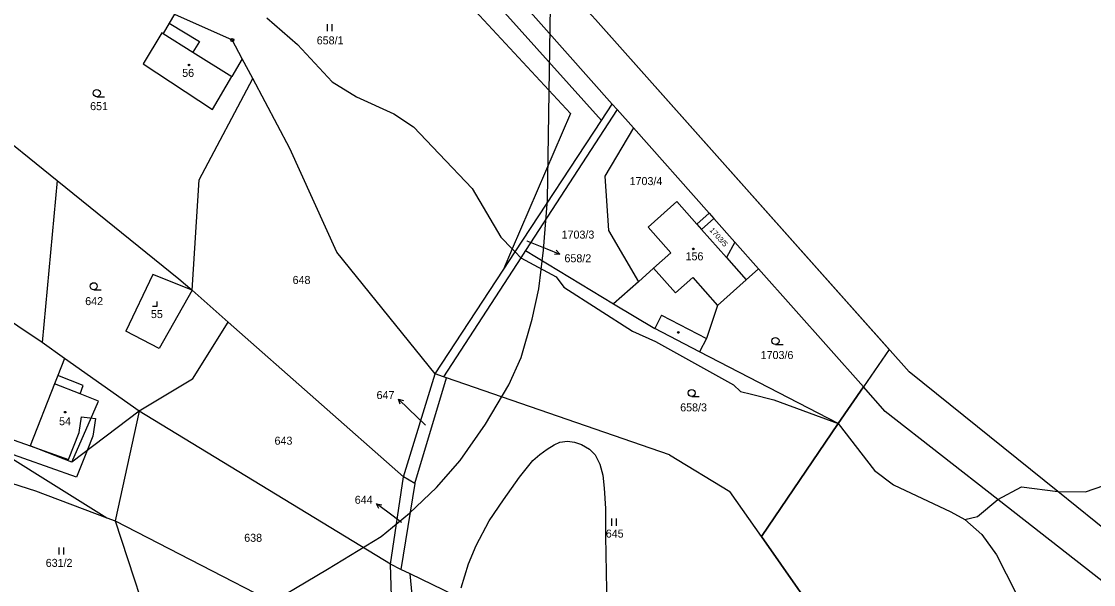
# Model space of a CAD drawing. Extents: x -546762 to -540209, y -1046851 to -1035694.
# Drawn here: x -544180.8 to -543953, y -1042709.8 to -1042590.2 of the extents above; entities that cross this region are included whole.
import ezdxf

# ---------------------------------------------------------------- set-up
doc = ezdxf.new("R2010")
doc.units = 0
for name, color, linetype in [('Vrstva 1', 7, 'Continuous'), ('Vrstva 16', 7, 'Continuous'), ('Vrstva 18', 7, 'Continuous'), ('Vrstva 19', 7, 'Continuous'), ('Vrstva 24', 7, 'Continuous'), ('Vrstva 25', 7, 'Continuous'), ('Vrstva 3', 7, 'Continuous'), ('Vrstva 30', 7, 'Continuous'), ('Vrstva 37', 7, 'Continuous'), ('Vrstva 4', 7, 'Continuous'), ('Vrstva 52', 7, 'Continuous')]:
    doc.layers.add(name, color=color, linetype=linetype)

msp = doc.modelspace()

# ---------------------------------------------------------------- linework, layer by layer
at = {"layer": 'Vrstva 1'}
for points in [[(-544055.22, -1042607.7), (-544128.99, -1042524.65)], [(-544133.73, -1042526.32), (-544057.53, -1042611.21)], [(-544064.09, -1042609.7), (-544135.03, -1042533.32)], [(-544148.22, -1042588.65), (-544149.36, -1042590.55)], [(-544148.22, -1042588.65), (-544135.96, -1042594.1)], [(-544149.36, -1042590.55), (-544150.68, -1042592.73)], [(-543992.15, -1042664.59), (-544058.8, -1042589.78)], [(-544150.93, -1042592.57), (-544154.93, -1042599.2)], [(-544150.68, -1042592.73), (-544150.93, -1042592.57)], [(-544133.85, -1042598.08), (-544135.96, -1042594.1)], [(-544133.85, -1042598.08), (-544136.06, -1042601.86)], [(-544131.62, -1042602.28), (-544133.85, -1042598.08)], [(-544154.93, -1042599.2), (-544140.19, -1042608.89)], [(-544142.98, -1042623.77), (-544131.62, -1042602.28)], [(-544140.19, -1042608.89), (-544136.06, -1042601.86)], [(-544123.71, -1042617.13), (-544131.62, -1042602.28)], [(-544054.18, -1042608.88), (-544073.66, -1042638.83)], [(-544057.53, -1042611.21), (-544055.22, -1042607.7)], [(-544054.18, -1042608.88), (-544055.22, -1042607.7)], [(-544050.73, -1042612.77), (-544054.18, -1042608.88)], [(-544188.45, -1042611.64), (-544173.21, -1042623.91)], [(-544064.09, -1042609.7), (-544076.47, -1042638.47)], [(-544075.86, -1042639.09), (-544057.53, -1042611.21)], [(-544050.73, -1042612.77), (-544056.83, -1042622.99)], [(-544034.62, -1042630.89), (-544050.73, -1042612.77)], [(-544113.77, -1042639.15), (-544123.71, -1042617.13)], [(-544056.83, -1042622.99), (-544055.99, -1042634.56)], [(-544173.21, -1042623.91), (-544176.39, -1042658.34)], [(-544173.21, -1042623.91), (-544147.29, -1042644.79)], [(-544144.5, -1042647.26), (-544142.98, -1042623.77)], [(-544041.49, -1042628.43), (-544047.62, -1042633.88)], [(-544041.49, -1042628.43), (-544037.23, -1042633.22)], [(-544037.23, -1042633.22), (-544034.62, -1042630.89)], [(-544033.62, -1042632.01), (-544036.24, -1042634.34)], [(-544034.62, -1042630.89), (-544033.62, -1042632.01)], [(-544033.62, -1042632.01), (-544029.17, -1042637.02)], [(-544055.99, -1042634.56), (-544049.65, -1042645.44)], [(-544042.77, -1042639.33), (-544047.62, -1042633.88)], [(-544036.24, -1042634.34), (-544030.92, -1042640.32)], [(-544176.39, -1042658.34), (-544207.91, -1042637.28)], [(-544076.47, -1042638.47), (-544078.4, -1042642.96)], [(-544078.4, -1042642.96), (-544075.86, -1042639.09)], [(-544073.66, -1042638.83), (-544074.63, -1042640.33)], [(-544073.66, -1042638.83), (-544054.93, -1042650.14)], [(-544029.17, -1042637.02), (-544030.92, -1042640.32)], [(-544024.13, -1042642.7), (-544029.17, -1042637.02)], [(-544092.88, -1042664.98), (-544113.77, -1042639.15)], [(-544074.63, -1042640.33), (-544091.08, -1042665.61)], [(-544042.77, -1042639.33), (-544046.43, -1042642.59)], [(-544092.88, -1042664.98), (-544078.4, -1042642.96)], [(-544049.65, -1042645.44), (-544046.43, -1042642.59)], [(-544024.13, -1042642.7), (-544026.74, -1042645.02)], [(-544001.87, -1042667.74), (-544024.13, -1042642.7)], [(-544152.88, -1042643.91), (-544158.62, -1042655.95)], [(-544144.5, -1042647.26), (-544152.88, -1042643.91)], [(-544147.29, -1042644.79), (-544144.5, -1042647.26)], [(-544049.65, -1042645.44), (-544054.93, -1042650.14)], [(-544026.74, -1042645.02), (-544032.87, -1042650.47)], [(-544144.5, -1042647.26), (-544151.47, -1042659.65)], [(-544144.5, -1042647.26), (-544136.85, -1042654.01)], [(-544054.93, -1042650.14), (-544046.2, -1042655.4)], [(-544032.87, -1042650.47), (-544035.23, -1042657.49)], [(-544144.45, -1042666.13), (-544136.85, -1042654.01)], [(-544136.85, -1042654.01), (-544099.59, -1042686.9)], [(-544151.47, -1042659.65), (-544158.62, -1042655.95)], [(-544036.7, -1042660.33), (-544046.2, -1042655.4)], [(-544171.61, -1042661.72), (-544176.39, -1042658.34)], [(-544035.23, -1042657.49), (-544036.7, -1042660.33)], [(-544171.61, -1042661.72), (-544173.03, -1042665.32)], [(-544155.75, -1042672.96), (-544171.61, -1042661.72)], [(-544007.21, -1042675.58), (-544036.7, -1042660.33)], [(-544173.03, -1042665.32), (-544173.73, -1042667.09)], [(-544144.45, -1042666.13), (-544155.75, -1042672.96)], [(-544099.59, -1042686.9), (-544092.88, -1042664.98)], [(-544097.16, -1042688.29), (-544090.46, -1042665.82)], [(-544091.08, -1042665.61), (-544092.88, -1042664.98)], [(-544090.46, -1042665.82), (-544091.08, -1042665.61)], [(-544043.06, -1042682.21), (-544090.46, -1042665.82)], [(-543960.57, -1042690), (-543992.15, -1042664.59)], [(-544173.73, -1042667.09), (-544178.93, -1042680.29)], [(-544007.21, -1042675.58), (-544001.87, -1042667.74)], [(-543997.22, -1042672.98), (-544001.87, -1042667.74)], [(-544155.75, -1042672.96), (-544170.09, -1042683.77)], [(-544155.75, -1042672.96), (-544160.83, -1042696.24)], [(-544102.35, -1042705.45), (-544155.75, -1042672.96)], [(-543973.27, -1042691.69), (-543997.22, -1042672.98)], [(-544195.2, -1042675.26), (-544162.65, -1042695.55)], [(-544023.53, -1042699.54), (-544007.21, -1042675.58)], [(-544170.09, -1042683.77), (-544178.93, -1042680.29)], [(-544043.06, -1042682.21), (-544030.21, -1042689.97)], [(-544195.32, -1042684.29), (-544177.77, -1042689.84)], [(-544102.35, -1042705.45), (-544099.59, -1042686.9)], [(-544097.16, -1042688.29), (-544099.59, -1042686.9)], [(-544097.16, -1042688.29), (-544100.14, -1042706.52)], [(-544177.77, -1042689.84), (-544162.65, -1042695.55)], [(-544023.53, -1042699.54), (-544030.21, -1042689.97)], [(-543944.41, -1042703), (-543960.57, -1042690)], [(-543951.18, -1042708.96), (-543973.27, -1042691.69)], [(-544162.65, -1042695.55), (-544160.83, -1042696.24)], [(-544160.83, -1042696.24), (-544108.35, -1042723.28)], [(-544160.83, -1042696.24), (-544151.55, -1042724.51)], [(-544007.6, -1042722.34), (-544023.53, -1042699.54)], [(-544102, -1042716.81), (-544102.35, -1042705.45)], [(-544100.14, -1042706.52), (-544102.35, -1042705.45)], [(-544098.16, -1042707.48), (-544100.14, -1042706.52)], [(-544064.86, -1042723.62), (-544098.16, -1042707.48)], [(-544097.26, -1042717.14), (-544098.16, -1042707.48)]]:
    msp.add_lwpolyline(points, dxfattribs=at)
at = {"layer": 'Vrstva 16'}
for p, q in [((-544069.15, -1042638.47), (-544066.38, -1042639.61)), ((-544098.52, -1042672.44), (-544100.68, -1042670.36)), ((-544102.91, -1042694.4), (-544105.31, -1042692.6))]:
    msp.add_line(p, q, dxfattribs=at)
for points in [[(-544073.39, -1042636.72), (-544069.15, -1042638.47)], [(-544067.11, -1042638.77), (-544066.38, -1042639.61), (-544067.49, -1042639.69)], [(-544100.31, -1042671.41), (-544100.68, -1042670.36), (-544099.61, -1042670.69)], [(-544094.94, -1042675.89), (-544098.52, -1042672.44)], [(-544104.81, -1042693.6), (-544105.31, -1042692.6), (-544104.21, -1042692.8)], [(-544100.04, -1042696.55), (-544102.91, -1042694.4)]]:
    msp.add_lwpolyline(points, dxfattribs=at)
at = {"layer": 'Vrstva 24'}
for radius in [0.335, 0.067]:
    msp.add_circle((-544135.96, -1042594.1), radius, dxfattribs=at)
at = {"layer": 'Vrstva 25'}
for p, q in [((-544115.75, -1042592.23), (-544115.75, -1042590.73)), ((-544114.75, -1042592.23), (-544114.75, -1042590.73)), ((-544164.75, -1042606.14), (-544163.15, -1042606.14)), ((-544165.41, -1042647.14), (-544163.81, -1042647.14)), ((-544020.54, -1042658.77), (-544018.94, -1042658.77)), ((-544038.35, -1042669.82), (-544036.75, -1042669.82)), ((-544055.35, -1042697.25), (-544055.35, -1042695.75)), ((-544054.35, -1042697.25), (-544054.35, -1042695.75)), ((-544172.75, -1042703.38), (-544172.75, -1042701.88)), ((-544171.75, -1042703.38), (-544171.75, -1042701.88))]:
    msp.add_line(p, q, dxfattribs=at)
msp.add_lwpolyline([(-544152.93, -1042650.64), (-544151.93, -1042650.64), (-544151.93, -1042649.64)], dxfattribs=at)
for centre, radius in [((-544145.16, -1042599.4), 0.175), ((-544164.75, -1042605.39), 0.75), ((-544038.01, -1042638.46), 0.175), ((-544165.41, -1042646.39), 0.75), ((-544041.2, -1042656.21), 0.175), ((-544020.54, -1042658.02), 0.75), ((-544038.35, -1042669.07), 0.75), ((-544171.46, -1042673.14), 0.175)]:
    msp.add_circle(centre, radius, dxfattribs=at)
at = {"layer": 'Vrstva 3'}
for points in [[(-544150.93, -1042592.57), (-544154.93, -1042599.2)], [(-544150.68, -1042592.73), (-544150.93, -1042592.57)], [(-544150.68, -1042592.73), (-544144.38, -1042596.67)], [(-544144.38, -1042596.67), (-544136.06, -1042601.86)], [(-544154.93, -1042599.2), (-544140.19, -1042608.89)], [(-544140.19, -1042608.89), (-544136.06, -1042601.86)], [(-544041.49, -1042628.43), (-544047.62, -1042633.88)], [(-544041.49, -1042628.43), (-544037.23, -1042633.22)], [(-544042.77, -1042639.33), (-544047.62, -1042633.88)], [(-544037.23, -1042633.22), (-544036.24, -1042634.34)], [(-544036.24, -1042634.34), (-544030.92, -1042640.32)], [(-544042.77, -1042639.33), (-544046.43, -1042642.59)], [(-544030.92, -1042640.32), (-544026.74, -1042645.02)], [(-544041.78, -1042647.82), (-544046.43, -1042642.59)], [(-544041.78, -1042647.82), (-544038.12, -1042644.56)], [(-544038.12, -1042644.56), (-544032.87, -1042650.47)], [(-544026.74, -1042645.02), (-544032.87, -1042650.47)], [(-544173.73, -1042667.09), (-544178.93, -1042680.29)], [(-544168.31, -1042669.22), (-544173.73, -1042667.09)], [(-544170.09, -1042683.77), (-544164.38, -1042670.77)], [(-544164.38, -1042670.77), (-544168.31, -1042669.22)], [(-544170.09, -1042683.77), (-544178.93, -1042680.29)]]:
    msp.add_lwpolyline(points, dxfattribs=at)
at = {"layer": 'Vrstva 30'}
msp.add_lwpolyline([(-544202.44, -1042672.02), (-544178.93, -1042680.29), (-544170.8, -1042683.2), (-544168.49, -1042677.48), (-544168.02, -1042674.1), (-544165.05, -1042674.51), (-544165.57, -1042678.26), (-544166.79, -1042681.28), (-544169.1, -1042686.98), (-544185.94, -1042681.03), (-544195.2, -1042675.26), (-544203.09, -1042672.07), (-544202.44, -1042672.02)], dxfattribs=at)
at = {"layer": 'Vrstva 37'}
for centre in [(-544145.16, -1042599.4), (-544038.01, -1042638.46), (-544171.46, -1042673.14)]:
    msp.add_circle(centre, 0.175, dxfattribs=at)
at = {"layer": 'Vrstva 4'}
for points in [[(-544149.36, -1042590.55), (-544142.96, -1042594.41)], [(-544128.65, -1042589.37), (-544122.12, -1042595.06)], [(-544150.68, -1042592.73), (-544144.38, -1042596.67)], [(-544142.96, -1042594.41), (-544144.38, -1042596.67)], [(-544122.12, -1042595.06), (-544114.72, -1042602.98)], [(-544144.38, -1042596.67), (-544136.06, -1042601.86)], [(-544114.72, -1042602.98), (-544109.59, -1042606.14)], [(-544109.59, -1042606.14), (-544101.62, -1042609.76)], [(-544101.62, -1042609.76), (-544097.48, -1042612.51)], [(-544097.48, -1042612.51), (-544091.99, -1042618.31)], [(-544091.99, -1042618.31), (-544084.99, -1042625.67)], [(-544084.99, -1042625.67), (-544078.93, -1042635.99)], [(-544037.23, -1042633.22), (-544036.24, -1042634.34)], [(-544078.93, -1042635.99), (-544076.47, -1042638.47)], [(-544076.47, -1042638.47), (-544075.86, -1042639.09)], [(-544075.86, -1042639.09), (-544074.63, -1042640.33)], [(-544074.63, -1042640.33), (-544067.16, -1042644.41)], [(-544030.92, -1042640.32), (-544026.74, -1042645.02)], [(-544041.78, -1042647.82), (-544046.43, -1042642.59)], [(-544067.16, -1042644.41), (-544065.49, -1042646.6)], [(-544041.78, -1042647.82), (-544038.12, -1042644.56)], [(-544038.12, -1042644.56), (-544032.87, -1042650.47)], [(-544065.49, -1042646.6), (-544050.89, -1042655.91)], [(-544044.73, -1042652.56), (-544046.2, -1042655.4)], [(-544044.73, -1042652.56), (-544035.23, -1042657.49)], [(-544050.89, -1042655.91), (-544046.06, -1042658.1)], [(-544046.06, -1042658.1), (-544029.44, -1042667.35)], [(-544167.62, -1042667.46), (-544173.03, -1042665.32)], [(-544168.31, -1042669.22), (-544173.73, -1042667.09)], [(-544168.31, -1042669.22), (-544167.62, -1042667.46)], [(-544029.44, -1042667.35), (-544028.01, -1042668.73)], [(-544028.01, -1042668.73), (-544025.65, -1042669.31)], [(-544170.09, -1042683.77), (-544164.38, -1042670.77)], [(-544164.38, -1042670.77), (-544168.31, -1042669.22)], [(-544025.65, -1042669.31), (-544020.88, -1042670.52)], [(-544020.88, -1042670.52), (-544007.21, -1042675.58)], [(-544007.21, -1042675.58), (-543999.53, -1042685.51)], [(-543999.53, -1042685.51), (-543995.43, -1042688.6)], [(-543995.43, -1042688.6), (-543983.3, -1042694.32)], [(-543973.27, -1042691.69), (-543968.25, -1042688.97)], [(-543968.25, -1042688.97), (-543960.57, -1042690)], [(-543954.69, -1042690.05), (-543946.87, -1042687.34)], [(-543960.57, -1042690), (-543954.69, -1042690.05)], [(-543977.61, -1042695.33), (-543973.27, -1042691.69)], [(-543983.3, -1042694.32), (-543980.31, -1042695.91)], [(-543980.31, -1042695.91), (-543977.61, -1042695.33)], [(-543980.31, -1042695.91), (-543976.71, -1042699.11)], [(-543976.71, -1042699.11), (-543973.61, -1042703.41)], [(-543973.61, -1042703.41), (-543967.39, -1042715.57)]]:
    msp.add_lwpolyline(points, dxfattribs=at)
at = {"layer": 'Vrstva 52'}
for points in [[(-544017.46, -1042510.83), (-544018.75, -1042539.99), (-544006.86, -1042546.1), (-544016.14, -1042553.71), (-544032.97, -1042563.33), (-544060.37, -1042588.02), (-544058.8, -1042589.78), (-543996.4, -1042659.82), (-544001.87, -1042667.74), (-544007.21, -1042675.58), (-544023.53, -1042699.54), (-544007.6, -1042722.34), (-543994.35, -1042740.08), (-543978.53, -1042755.27), (-543969.68, -1042767.22), (-543967.35, -1042770.36), (-543961.17, -1042789.27), (-543956.03, -1042811.37), (-543954.4, -1042831.58), (-543959.26, -1042856.2), (-543982.29, -1042852.21), (-544009.18, -1042839.83), (-544057.02, -1042836.26), (-544068.37, -1042835.41)], [(-544131.24, -1042715.67), (-544115.74, -1042706.46), (-544104.35, -1042699.55), (-544098.3, -1042694.59), (-544092.6, -1042689.13), (-544087.52, -1042683.44), (-544082.19, -1042675.68), (-544077.22, -1042667.32), (-544074.56, -1042661.51), (-544072.26, -1042653.39), (-544070.8, -1042646.97), (-544069.84, -1042638.73), (-544069.01, -1042628.06), (-544068.38, -1042586.93)], [(-544087.33, -1042710.45), (-544085.74, -1042705.37), (-544084.15, -1042701.49), (-544081.38, -1042696.23), (-544078.34, -1042691.73), (-544074.94, -1042686.95), (-544072.11, -1042683.42), (-544070.59, -1042682.13), (-544069.04, -1042681.03), (-544067.58, -1042680.08), (-544066.35, -1042679.52), (-544064.77, -1042679.33), (-544063.27, -1042679.48)], [(-544063.27, -1042679.48), (-544061.73, -1042680), (-544060.03, -1042681.03), (-544058.84, -1042682.21), (-544057.85, -1042684.19), (-544057.22, -1042686.49), (-544056.94, -1042689.3), (-544056.63, -1042693.57), (-544056.67, -1042699.5), (-544056.29, -1042718.62)]]:
    msp.add_lwpolyline(points, dxfattribs=at)

# ---------------------------------------------------------------- texts
at = {"layer": 'Vrstva 16'}
for s, p in [('658/2', (-544065.38, -1042641.31)), ('647', (-544105.31, -1042670.36)), ('644', (-544109.94, -1042692.6))]:
    msp.add_text(s, height=1.7, dxfattribs=at).set_placement(p)
at = {"layer": 'Vrstva 18'}
for s, height, p in [('658/1', 1.7, (-544118.02, -1042595.03)), ('651', 1.7, (-544166.17, -1042609)), ('1703/4', 1.7, (-544051.54, -1042624.92)), ('1703/3', 1.7, (-544065.99, -1042636.28)), ('658/2', 0.1, (-544073.58, -1042636.72)), ('648', 1.7, (-544123.15, -1042645.91)), ('642', 1.7, (-544167.22, -1042650.41)), ('1703/6', 1.7, (-544023.69, -1042661.86)), ('658/3', 1.7, (-544040.79, -1042672.98)), ('647', 0.1, (-544095.05, -1042675.89)), ('643', 1.7, (-544126.99, -1042680.05)), ('644', 0.1, (-544100.15, -1042696.55)), ('645', 1.7, (-544056.6, -1042699.78)), ('638', 1.7, (-544133.43, -1042700.67)), ('631/2', 1.7, (-544175.61, -1042706))]:
    msp.add_text(s, height=height, dxfattribs=at).set_placement(p)
msp.add_text('1703/5', height=1.14, rotation=312.0914, dxfattribs=at).set_placement((-544034.64, -1042634.54))
at = {"layer": 'Vrstva 19'}
for s, p in [('56', (-544146.61, -1042601.94)), ('156', (-544039.65, -1042640.89)), ('55', (-544153.26, -1042653.16)), ('54', (-544172.77, -1042675.92))]:
    msp.add_text(s, height=1.7, dxfattribs=at).set_placement(p)

doc.saveas('drawing.dxf')
